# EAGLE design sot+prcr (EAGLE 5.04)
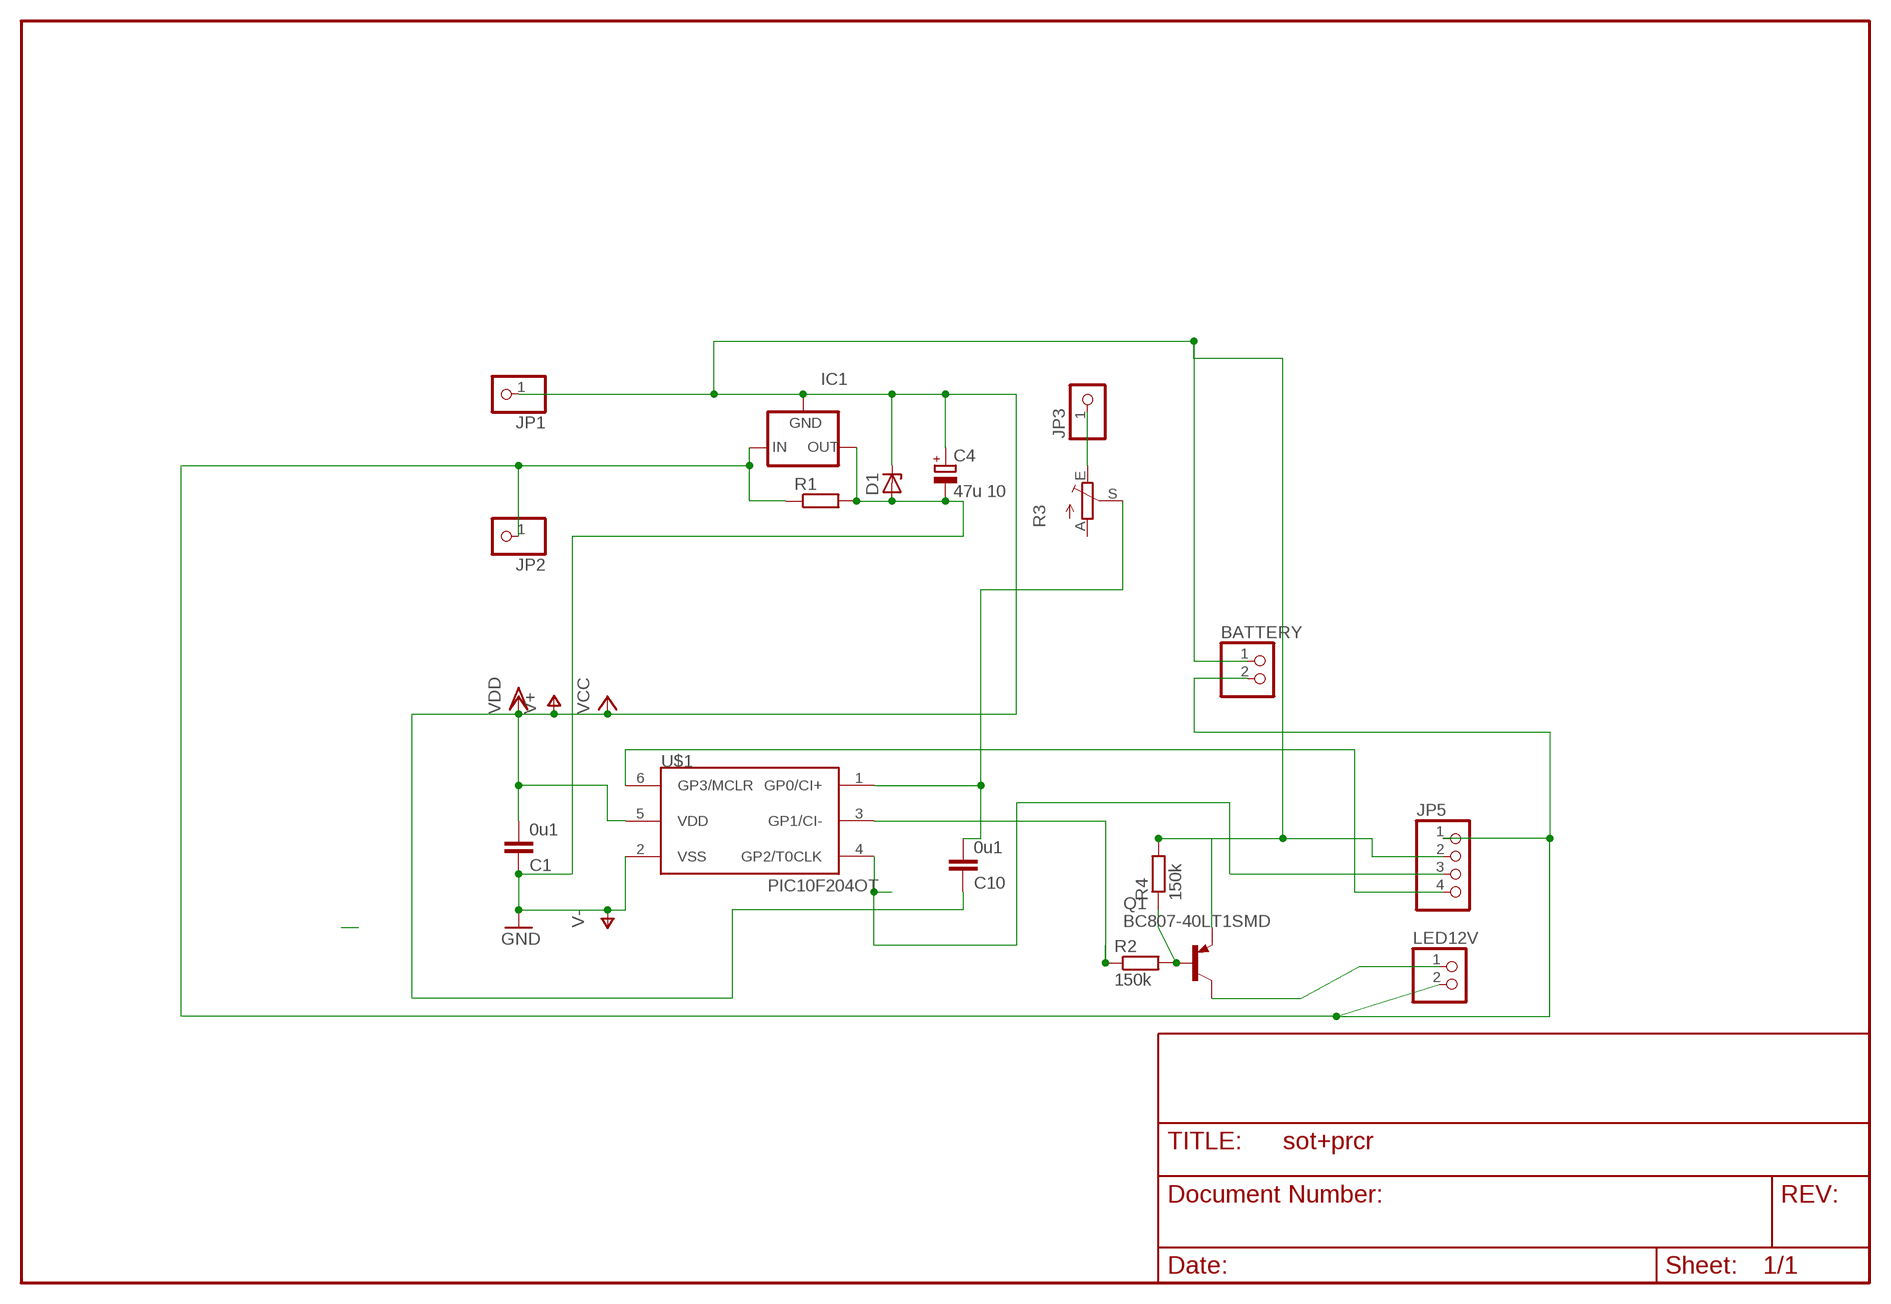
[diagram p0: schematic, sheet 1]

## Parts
BATTERY  PINHD-1X2  [1X02]
C1  0u1  C-EUC1206  [C1206]
C4  47u 10  CPOL-EUE2.5-6  [E2,5-6]
C10  0u1  C-EUC1206  [C1206]
D1  ZENER-DIODESOT23  [SOT23]
IC1  79LXX  [79LXX]
JP1  PINHD-1X1  [1X01]
JP2  PINHD-1X1  [1X01]
JP3  PINHD-1X1  [1X01]
JP5  PINHD-1X4  [1X04]
LED12V  PINHD-1X2  [1X02]
Q1  BC807-40LT1SMD  [SOT23-BEC]
R1  R-EU_R0805  [R0805]
R2  150k  R-EU_R0805  [R0805]
R3  TRIM_EU-CA6V  [CA6V]
R4  150k  R-EU_R0805  [R0805]
U$1  PIC10F204OT  [SOT23-6]

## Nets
GND: C1.1 C4.- D1.1(A) IC1.OUT R1.2 U$1.2(VSS) ; supply symbol labelled V-
N$1: JP3.1 R3.E
N$2: JP5.3 U$1.4(GP2/T0CLK)
N$3: JP5.4 U$1.6(GP3/MCLR)
N$4: Q1.B R2.2 R4.1
N$7: BATTERY.2 IC1.IN JP2.1 JP5.1 LED12V.2 R1.1
N$8: R2.1 U$1.3(GP1/CI-)
N$9: LED12V.1 Q1.C
N$12: C10.2 R3.S U$1.1(GP0/CI+)
V+: BATTERY.1 C1.2 C4.+ C10.1 D1.3(C) IC1.GND JP1.1 JP5.2 Q1.E R4.2 U$1.5(VDD) ; supply symbol labelled VDD, VCC
Unconnected: R3.A

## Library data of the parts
BATTERY LED12V = pinhead:PINHD-1X2: PIN HEADER
C1 C10 = rcl:C-EU: CAPACITOR, European symbol
C4 = rcl:CPOL-EU: POLARIZED CAPACITOR, European symbol
D1 = diode-1:ZENER-DIODE: Z-Diode
IC1 = v-reg:79LXX: VOLTAGE REGULATOR
JP1-JP3 = pinhead:PINHD-1X1: PIN HEADER
JP5 = pinhead(2):PINHD-1X4: PIN HEADER
Q1 = transistor-pnp:BC807*: PNP Transistror
R1 = rcl-2:R-EU_: RESISTOR, European symbol
R2 R4 = rcl:R-EU_: RESISTOR, European symbol
R3 = pot:TRIM_EU-: POTENTIOMETER
U$1 = microchip-5:PIC10F2*: uPC nW 0,25/0,5k Program Flash memory Comparator

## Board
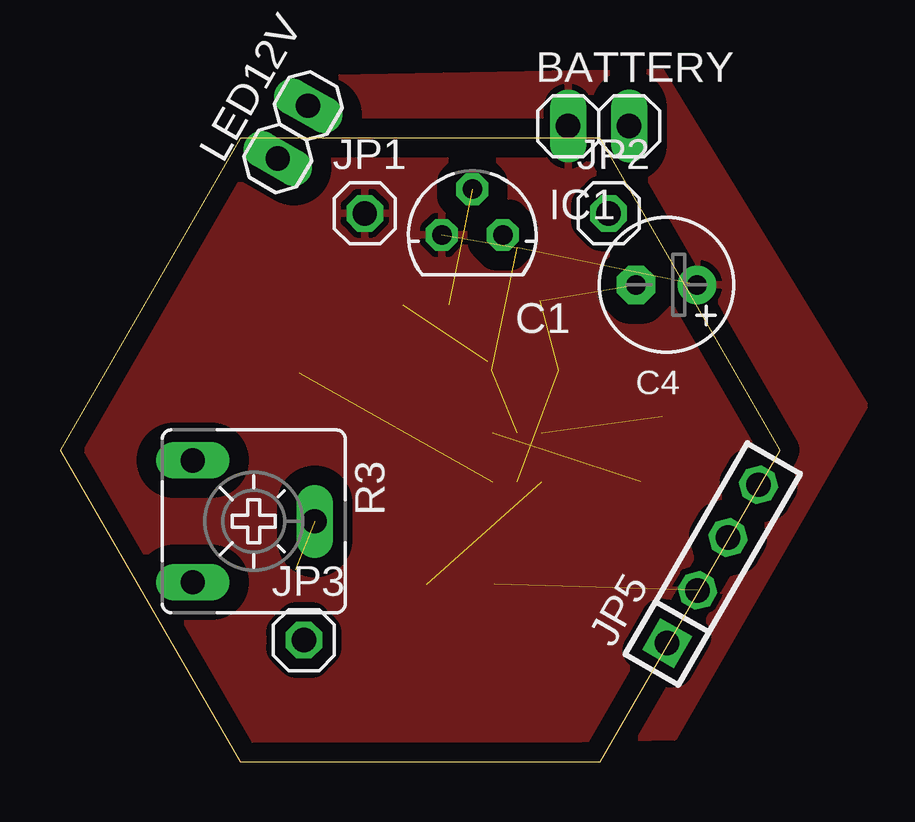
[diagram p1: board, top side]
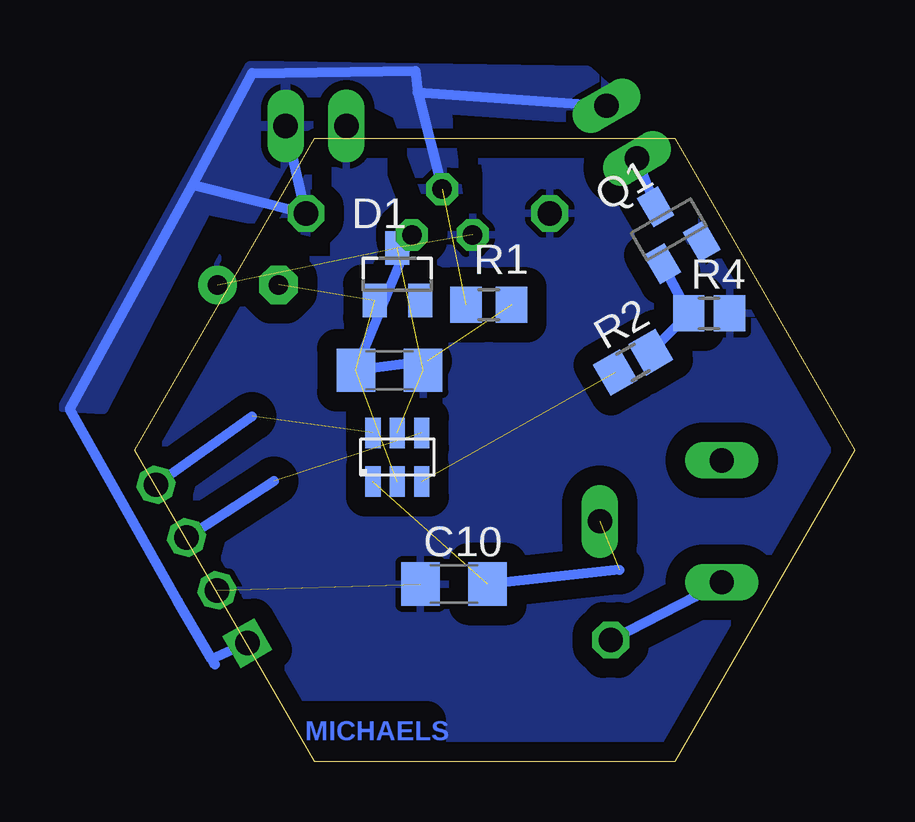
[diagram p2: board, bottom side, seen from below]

Size 30 x 25.98 mm. Coordinates in mm from the lower left corner, seen from the top.
Outline: 7.5,0 22.5,0 30,12.99 22.5,25.98 7.5,25.98 0,12.99 7.5,0
Copper layers (1*16): Top 0.035mm / dielectric 1.5mm / Bottom 0.035mm
Design rules "default *": minimum track width 10mil, minimum drill 24mil, track to track 8mil, track to pad 8mil, pad to pad 8mil, via to via 8mil, smd to smd 8mil, copper to edge 10mil, drill to drill 8mil, minimum pad ring 10mil, minimum via ring 8mil, stop-mask expansion 4mil, vias tented up to drill 0mil, thermal gap 10mil

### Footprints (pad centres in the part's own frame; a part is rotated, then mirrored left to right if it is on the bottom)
1X02 = drill 1.016 long: 1 -1.27,0; 2 1.27,0
C1206 = smd 1.6 x 1.8: 1 -1.4,0; 2 1.4,0
E2,5-6 = drill 0.813 pad 1.6 round: + -1.27,0 | drill 0.813 pad 1.6 octagon: - 1.27,0
SOT23 = smd 1 x 1.4: 1 -0.95,-1.1; 2 0.95,-1.1; 3 0,1.1
79LXX = drill 0.813 octagon: GND -1.27,0; IN 0,1.905; OUT 1.27,0
1X01 = drill 1.016 octagon: 1 0,0
1X04 = drill 1.016 square: 1 -3.81,0 | drill 1.016 octagon: 2 -1.27,0; 3 1.27,0; 4 3.81,0
SOT23-BEC = smd 1 x 1.4: B -0.95,-1.1; C 0,1.1; E 0.95,-1.1
R0805 = smd 1.3 x 1.5: 1 -0.95,0; 2 0.95,0
R0805' = smd 1.3 x 1.5: 1 -0.85,0; 2 0.85,0
CA6V = drill 1.016 long: A -2.54,-2.54; E 2.54,-2.54; S 0,2.54
SOT23-6 = smd 0.635 x 1.27: 1 -1.016,-1.016; 2 0,-1.016; 3 1.016,-1.016; 4 1.016,1.016; 5 0,1.016; 6 -1.016,1.016

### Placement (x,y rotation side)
BATTERY  22.44,26.49 0 top
C1  19.38,16.32 0 bottom
C4  25.27,19.88 180 top
C10  16.69,7.41 0 bottom
D1  19.05,20.32 0 bottom
IC1  17.18,21.96 0 top
JP1  12.7,22.86 0 top
JP2  22.86,22.86 0 top
JP3  10.16,5.08 0 top
JP5  27.2,8.25 60 top
LED12V  9.71,26.24 60 top
Q1  7.74,22.18 30 bottom
R1  15.24,19.05 0 bottom
R2  150k  [R0805']  9.23,16.65 30 bottom
R3  8.07,10.03 270 top
R4  150k  [R0805']  6.06,18.69 0 bottom
U$1  19.05,12.7 0 bottom

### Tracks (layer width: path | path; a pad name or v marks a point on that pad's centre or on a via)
GND  (4 unrouted)
  Bottom 0.406: 17.8,16.7 C1.1 IC1.OUT
N$1
  Bottom 0.406: JP3.1 6.6,6.9 R3.E
N$2  (1 unrouted)
  Bottom 0.406: JP5.3 24.2,11.7
N$3  (1 unrouted)
  Bottom 0.406: 25.1,14.4 JP5.4
N$4
  Bottom 0.406: Q1.B R4.1 R2.2
N$7  (1 unrouted)
  Bottom 0.406: 26.78,4.27 26.65,4.05 | 26.78,4.27 28.2,6.7 32.7,14.7 27.58,24.05 | 27.58,24.05 25.1,28.7 18.3,28.8 18.2,27.9 | 18.2,27.9 IC1.IN | 18.2,27.9 LED12V.2 | 27.58,24.05 JP2.1 BATTERY.2 | JP5.1 26.78,4.27
  pour Bottom (isolate 0.406, rank 2): 10.16,27.94 11.1,28.8 25.2,29 33,14.8 31.3,14.7 27,23 22.6,22.1 22.8,24.1 22.7,27.9 20.9,27.9 19.1,27 17.8,23.5 16.5,23.5 17,27.2 11.3,26.8
N$8  (1 unrouted)
N$9
  Bottom 0.406: LED12V.1 Q1.C
N$12  (2 unrouted)
  Bottom 0.406: 9.8,8 C10.2
V+  (5 unrouted)
  pour Bottom (isolate 0.813, rank 4): 25.09,0.65 6.94,0.85 -0.63,14.71 7.94,28.25 23.9,28.98 28.25,24.24 33.14,13.91
  pour Top (isolate 0.813, rank 4): 25.05,28.74 33.52,14.83 25.59,1.05 7.24,0.65 -0.28,14.57 9.11,28.44

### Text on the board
Bottom: MICHAELS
